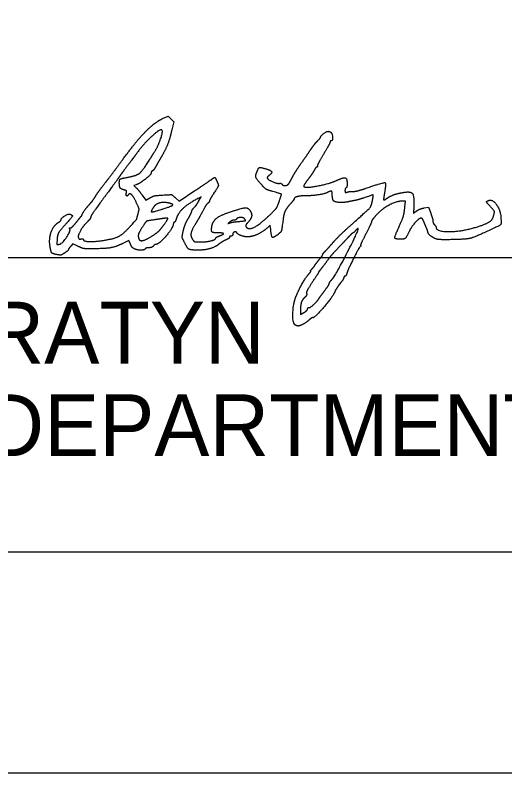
# Model space of a CAD drawing. Extents: x -21.1 to 50.3, y 0 to 22.1.
# Drawn here: x 25.904 to 27.013, y 0 to 1.718 of the extents above; entities that cross this region are included whole.
import ezdxf

# ---------------------------------------------------------------- set-up
doc = ezdxf.new("R2010")
doc.units = 0
for name, color, linetype in [('Default', 7, 'Continuous'), ('SH_Border', 7, 'Continuous'), ('SH_Cut_Line', 7, 'Continuous'), ('SH_Data', 7, 'Continuous'), ('SH_Text', 7, 'Continuous')]:
    doc.layers.add(name, color=color, linetype=linetype)

msp = doc.modelspace()

# ---------------------------------------------------------------- linework, layer by layer
at = {"layer": 'Default'}
for points in [[(26.2376, 1.4833), (26.2502, 1.4891), (26.2566, 1.4828), (26.2629, 1.4764), (26.2585, 1.4577)], [(26.1777, 1.3333), (26.1727, 1.3317), (26.1778, 1.3266)], [(26.1915, 1.3099), (26.2, 1.2984), (26.2088, 1.3036)], [(26.2666, 1.3036), (26.2748, 1.296), (26.311, 1.3201)], [(26.3205, 1.2983), (26.325, 1.3063), (26.3195, 1.3033)], [(26.7864, 1.2824), (26.7879, 1.2962), (26.78, 1.2962)], [(26.8302, 1.2808), (26.8399, 1.2823), (26.845, 1.2688)], [(26.4823, 1.2346), (26.4816, 1.2415), (26.4757, 1.2363)], [(26.1647, 1.199), (26.1613, 1.2071), (26.1475, 1.2002)], [(26.046, 1.194), (26.0345, 1.1998), (26.0295, 1.194)], [(26.55, 1.0485), (26.55, 1.0391), (26.5576, 1.0435)]]:
    msp.add_lwpolyline(points, dxfattribs=at)
for points in [[(26.148, 1.3914), (26.1777, 1.432), (26.2195, 1.4749), (26.2376, 1.4833)], [(26.2361, 1.4575), (26.2325, 1.4611), (26.1939, 1.4254), (26.1786, 1.4041)], [(26.2178, 1.4054), (26.2273, 1.4203), (26.2392, 1.4544), (26.2361, 1.4575)], [(26.2585, 1.4577), (26.2536, 1.4365), (26.2444, 1.4129), (26.235, 1.397)], [(26.5956, 1.4413), (26.5956, 1.4442), (26.6088, 1.4545), (26.6126, 1.4545)], [(26.6126, 1.4545), (26.6146, 1.4546), (26.6176, 1.4533), (26.6192, 1.4517)], [(26.6192, 1.4517), (26.6226, 1.4483), (26.623, 1.433), (26.6196, 1.433)], [(26.5752, 1.416), (26.5792, 1.4219), (26.5854, 1.4296), (26.589, 1.4332)], [(26.589, 1.4332), (26.5927, 1.4369), (26.5956, 1.4405), (26.5956, 1.4413)], [(26.6172, 1.4305), (26.6172, 1.4291), (26.6108, 1.417), (26.6028, 1.4036)], [(26.6196, 1.433), (26.6183, 1.433), (26.6172, 1.4319), (26.6172, 1.4305)], [(26.5536, 1.385), (26.5616, 1.3962), (26.5713, 1.4102), (26.5752, 1.416)], [(26.1786, 1.4041), (26.175, 1.3991), (26.1656, 1.3865), (26.1576, 1.376)], [(26.2073, 1.3887), (26.2106, 1.394), (26.2153, 1.4015), (26.2178, 1.4054)], [(26.235, 1.397), (26.2314, 1.3911), (26.2262, 1.3819), (26.2234, 1.3766)], [(26.6028, 1.4036), (26.5949, 1.3902), (26.5884, 1.3779), (26.5884, 1.3761)], [(26.1079, 1.3379), (26.1168, 1.3493), (26.1348, 1.3733), (26.148, 1.3914)], [(26.1576, 1.376), (26.1497, 1.3655), (26.1416, 1.3545), (26.1396, 1.3515)], [(26.1575, 1.3501), (26.1781, 1.3538), (26.1922, 1.3647), (26.2073, 1.3887)], [(26.2234, 1.3766), (26.2205, 1.3713), (26.2167, 1.3662), (26.2149, 1.3651)], [(26.5322, 1.3514), (26.5361, 1.3587), (26.5457, 1.3738), (26.5536, 1.385)], [(26.5884, 1.3761), (26.5884, 1.3744), (26.5875, 1.373), (26.5864, 1.373)], [(26.2116, 1.3597), (26.2116, 1.3559), (26.1859, 1.3359), (26.1777, 1.3333)], [(26.2149, 1.3651), (26.2131, 1.364), (26.2116, 1.3616), (26.2116, 1.3597)], [(26.4614, 1.3338), (26.4499, 1.3469), (26.4476, 1.3537), (26.4516, 1.3633)], [(26.4516, 1.3633), (26.4553, 1.3723), (26.4585, 1.3733), (26.4712, 1.3696)], [(26.4712, 1.3696), (26.4832, 1.366), (26.486, 1.3599), (26.4783, 1.354)], [(26.5812, 1.3664), (26.5794, 1.3628), (26.5733, 1.3537), (26.5676, 1.3462)], [(26.5864, 1.373), (26.5853, 1.373), (26.583, 1.37), (26.5812, 1.3664)], [(26.1396, 1.3515), (26.1377, 1.3486), (26.1223, 1.3276), (26.1055, 1.305)], [(26.1396, 1.338), (26.1396, 1.3448), (26.1437, 1.3476), (26.1575, 1.3501)], [(26.311, 1.3201), (26.3309, 1.3334), (26.3485, 1.3453), (26.3501, 1.3466)], [(26.3501, 1.3466), (26.3547, 1.3504), (26.357, 1.3495), (26.36, 1.3429)], [(26.36, 1.3429), (26.3644, 1.3333), (26.3635, 1.3292), (26.3532, 1.3133)], [(26.4783, 1.354), (26.4756, 1.3519), (26.4741, 1.3491), (26.4751, 1.3478)], [(26.4751, 1.3478), (26.4778, 1.344), (26.4977, 1.3358), (26.5023, 1.3366)], [(26.523, 1.3352), (26.5243, 1.3369), (26.5284, 1.3442), (26.5322, 1.3514)], [(26.5676, 1.3462), (26.5619, 1.3387), (26.5572, 1.3315), (26.5572, 1.3301)], [(26.5572, 1.3301), (26.5572, 1.3249), (26.6168, 1.3358), (26.6348, 1.3444)], [(26.6348, 1.3444), (26.6478, 1.3506), (26.6556, 1.3474), (26.6556, 1.336)], [(26.0863, 1.3086), (26.0893, 1.3134), (26.099, 1.3266), (26.1079, 1.3379)], [(26.1506, 1.3216), (26.1435, 1.3234), (26.1396, 1.3291), (26.1396, 1.338)], [(26.1778, 1.3266), (26.1806, 1.3237), (26.1868, 1.3162), (26.1915, 1.3099)], [(26.4848, 1.3187), (26.4741, 1.3218), (26.4691, 1.325), (26.4614, 1.3338)], [(26.5023, 1.3366), (26.5046, 1.3369), (26.5071, 1.3361), (26.508, 1.3347)], [(26.508, 1.3347), (26.5101, 1.3313), (26.5201, 1.3316), (26.523, 1.3352)], [(26.6532, 1.3262), (26.6519, 1.3254), (26.6508, 1.3226), (26.6508, 1.3199)], [(26.6556, 1.336), (26.6556, 1.3314), (26.6546, 1.327), (26.6532, 1.3262)], [(26.6692, 1.3183), (26.6733, 1.3181), (26.6863, 1.3213), (26.698, 1.3253)], [(26.698, 1.3253), (26.7383, 1.3392), (26.7443, 1.3375), (26.7401, 1.3137)], [(26.07, 1.2867), (26.0766, 1.294), (26.0809, 1.2997), (26.0863, 1.3086)], [(26.1557, 1.3153), (26.1566, 1.3189), (26.1554, 1.3204), (26.1506, 1.3216)], [(26.16, 1.3106), (26.1576, 1.3066), (26.1544, 1.3102), (26.1557, 1.3153)], [(26.1788, 1.2919), (26.1727, 1.3056), (26.1629, 1.3153), (26.16, 1.3106)], [(26.2088, 1.3036), (26.2154, 1.3075), (26.2229, 1.3091), (26.2381, 1.31)], [(26.2381, 1.31), (26.2584, 1.3112), (26.2585, 1.3112), (26.2666, 1.3036)], [(26.3532, 1.3133), (26.348, 1.3051), (26.3436, 1.2975), (26.3436, 1.2964)], [(26.5016, 1.2949), (26.5073, 1.3118), (26.5069, 1.3123), (26.4848, 1.3187)], [(26.5599, 1.3082), (26.5484, 1.3082), (26.5356, 1.3044), (26.5356, 1.301)], [(26.6106, 1.3156), (26.605, 1.3126), (26.5748, 1.3082), (26.5599, 1.3082)], [(26.622, 1.3109), (26.622, 1.3182), (26.6183, 1.3197), (26.6106, 1.3156)], [(26.6414, 1.2932), (26.6289, 1.2933), (26.622, 1.2996), (26.622, 1.3109)], [(26.6508, 1.3199), (26.6508, 1.316), (26.6519, 1.3154), (26.6562, 1.3168)], [(26.6562, 1.3168), (26.6592, 1.3178), (26.665, 1.3184), (26.6692, 1.3183)], [(26.7132, 1.2987), (26.7153, 1.3102), (26.7136, 1.3106), (26.6926, 1.3033)], [(26.7401, 1.3137), (26.7388, 1.3061), (26.7381, 1.2994), (26.7385, 1.299)], [(26.7461, 1.3028), (26.7533, 1.3079), (26.7716, 1.3142), (26.7852, 1.3163)], [(26.7852, 1.3163), (26.7999, 1.3186), (26.8075, 1.3082), (26.8068, 1.287)], [(26.1055, 1.305), (26.0887, 1.2823), (26.0749, 1.2622), (26.0748, 1.2602)], [(26.1821, 1.2674), (26.1847, 1.2772), (26.1844, 1.2795), (26.1788, 1.2919)], [(26.2498, 1.2923), (26.239, 1.2945), (26.2216, 1.2894), (26.2173, 1.2828)], [(26.2392, 1.2788), (26.2585, 1.2847), (26.2625, 1.2898), (26.2498, 1.2923)], [(26.3195, 1.3033), (26.2961, 1.2908), (26.2733, 1.2701), (26.2692, 1.2577)], [(26.3077, 1.2802), (26.3132, 1.2862), (26.3157, 1.2897), (26.3205, 1.2983)], [(26.3401, 1.2915), (26.3381, 1.2898), (26.335, 1.2857), (26.3332, 1.2822)], [(26.3436, 1.2964), (26.3436, 1.2953), (26.342, 1.2931), (26.3401, 1.2915)], [(26.4833, 1.2676), (26.4937, 1.2777), (26.4979, 1.2839), (26.5016, 1.2949)], [(26.5263, 1.289), (26.5178, 1.2795), (26.5121, 1.267), (26.5105, 1.2542)], [(26.5356, 1.301), (26.5356, 1.3002), (26.5314, 1.2947), (26.5263, 1.289)], [(26.658, 1.2947), (26.6547, 1.2939), (26.6472, 1.2932), (26.6414, 1.2932)], [(26.6712, 1.2973), (26.6673, 1.2966), (26.6613, 1.2954), (26.658, 1.2947)], [(26.6684, 1.2457), (26.7039, 1.2773), (26.7108, 1.2854), (26.7132, 1.2987)], [(26.6926, 1.3033), (26.6848, 1.3006), (26.6752, 1.2979), (26.6712, 1.2973)], [(26.78, 1.2962), (26.7674, 1.2962), (26.7336, 1.2778), (26.7214, 1.2642)], [(26.7385, 1.299), (26.739, 1.2985), (26.7424, 1.3002), (26.7461, 1.3028)], [(26.9768, 1.2876), (26.9715, 1.2933), (26.9713, 1.2959), (26.9759, 1.2977)], [(26.9759, 1.2977), (26.9845, 1.301), (27.0029, 1.2761), (27.0039, 1.2598)], [(26.0556, 1.2662), (26.0556, 1.2678), (26.0648, 1.2809), (26.07, 1.2867)], [(26.2173, 1.2828), (26.2102, 1.2721), (26.2148, 1.2712), (26.2392, 1.2788)], [(26.2953, 1.2561), (26.2997, 1.2637), (26.3035, 1.2714), (26.3037, 1.2732)], [(26.3037, 1.2732), (26.304, 1.2749), (26.3058, 1.2781), (26.3077, 1.2802)], [(26.3332, 1.2822), (26.3251, 1.2667), (26.3173, 1.253), (26.3111, 1.2433)], [(26.387, 1.2705), (26.4189, 1.2811), (26.4323, 1.2815), (26.4373, 1.272)], [(26.4373, 1.272), (26.4406, 1.266), (26.4372, 1.2546), (26.4297, 1.2467)], [(26.7717, 1.2346), (26.7807, 1.2545), (26.7848, 1.2676), (26.7864, 1.2824)], [(26.8068, 1.287), (26.8061, 1.2686), (26.8059, 1.2689), (26.8137, 1.2744)], [(26.8137, 1.2744), (26.8175, 1.2771), (26.8249, 1.2799), (26.8302, 1.2808)], [(26.9859, 1.2585), (26.9899, 1.2703), (26.9884, 1.2752), (26.9768, 1.2876)], [(26.003, 1.2489), (26.0055, 1.2505), (26.0076, 1.2529), (26.0077, 1.2542)], [(26.0077, 1.2542), (26.0077, 1.2579), (26.0245, 1.2679), (26.0283, 1.2665)], [(26.0283, 1.2665), (26.0342, 1.2642), (26.0319, 1.2593), (26.0176, 1.2434)], [(26.0411, 1.247), (26.0465, 1.2536), (26.0519, 1.2603), (26.0532, 1.2619)], [(26.0532, 1.2619), (26.0546, 1.2635), (26.0556, 1.2654), (26.0556, 1.2662)], [(26.0748, 1.2602), (26.0748, 1.2582), (26.0714, 1.2534), (26.0674, 1.2495)], [(26.1624, 1.2369), (26.1785, 1.2545), (26.1788, 1.255), (26.1821, 1.2674)], [(26.2374, 1.2566), (26.2318, 1.2558), (26.224, 1.2546), (26.22, 1.254)], [(26.2424, 1.245), (26.2502, 1.2563), (26.2493, 1.2585), (26.2374, 1.2566)], [(26.2692, 1.2577), (26.2675, 1.2525), (26.2652, 1.2482), (26.264, 1.2482)], [(26.2844, 1.2282), (26.286, 1.2359), (26.2909, 1.2485), (26.2953, 1.2561)], [(26.3494, 1.2394), (26.3515, 1.2507), (26.3677, 1.2641), (26.387, 1.2705)], [(26.4047, 1.2551), (26.4039, 1.254), (26.4015, 1.253), (26.3991, 1.253)], [(26.4231, 1.2562), (26.4203, 1.2596), (26.4069, 1.2588), (26.4047, 1.2551)], [(26.4072, 1.2499), (26.424, 1.2514), (26.4264, 1.2524), (26.4231, 1.2562)], [(26.4263, 1.2388), (26.4317, 1.2301), (26.4584, 1.2437), (26.4833, 1.2676)], [(26.5105, 1.2542), (26.5076, 1.2317), (26.5059, 1.2262), (26.5002, 1.2218)], [(26.7214, 1.2642), (26.7156, 1.2578), (26.7108, 1.2512), (26.7108, 1.2496)], [(26.8232, 1.2578), (26.8189, 1.2578), (26.8007, 1.2373), (26.796, 1.2271)], [(26.8288, 1.2512), (26.8273, 1.2548), (26.8248, 1.2578), (26.8232, 1.2578)], [(26.845, 1.2688), (26.8477, 1.2613), (26.85, 1.2532), (26.85, 1.2507)], [(26.9371, 1.2342), (26.9607, 1.2404), (26.9837, 1.2518), (26.9859, 1.2585)], [(27.0039, 1.2598), (27.0049, 1.2445), (27.0022, 1.2413), (26.9788, 1.2304)], [(25.9828, 1.1926), (25.9798, 1.2111), (25.9906, 1.2411), (26.003, 1.2489)], [(26.0176, 1.2434), (26.0039, 1.2282), (25.9989, 1.2181), (25.9984, 1.2043)], [(26.0288, 1.2357), (26.0302, 1.2353), (26.0358, 1.2404), (26.0411, 1.247)], [(26.0674, 1.2495), (26.0576, 1.2399), (26.0452, 1.2177), (26.047, 1.2131)], [(26.1059, 1.2076), (26.1287, 1.2113), (26.1483, 1.2215), (26.1624, 1.2369)], [(26.1929, 1.239), (26.1847, 1.2264), (26.1816, 1.2166), (26.1838, 1.2108)], [(26.22, 1.254), (26.2023, 1.2514), (26.2002, 1.2503), (26.1929, 1.239)], [(26.2125, 1.2163), (26.2237, 1.2233), (26.2347, 1.2338), (26.2424, 1.245)], [(26.262, 1.2452), (26.2619, 1.2367), (26.2288, 1.1978), (26.2216, 1.1978)], [(26.264, 1.2482), (26.2629, 1.2482), (26.262, 1.2469), (26.262, 1.2452)], [(26.3111, 1.2433), (26.3032, 1.2307), (26.3009, 1.2154), (26.306, 1.2086)], [(26.363, 1.2242), (26.3515, 1.2242), (26.3474, 1.2288), (26.3494, 1.2394)], [(26.3903, 1.2492), (26.3857, 1.2455), (26.3857, 1.2455), (26.3904, 1.2471)], [(26.3991, 1.253), (26.3968, 1.253), (26.3929, 1.2513), (26.3903, 1.2492)], [(26.3904, 1.2471), (26.3931, 1.248), (26.4006, 1.2493), (26.4072, 1.2499)], [(26.4297, 1.2467), (26.427, 1.2438), (26.4254, 1.2402), (26.4263, 1.2388)], [(26.6243, 1.203), (26.6316, 1.2114), (26.6514, 1.2306), (26.6684, 1.2457)], [(26.7108, 1.2496), (26.7108, 1.2481), (26.7049, 1.2352), (26.6976, 1.2211)], [(26.8348, 1.2371), (26.833, 1.2412), (26.8303, 1.2476), (26.8288, 1.2512)], [(26.8381, 1.2275), (26.8381, 1.2286), (26.8366, 1.2329), (26.8348, 1.2371)], [(26.85, 1.2507), (26.85, 1.2482), (26.8517, 1.2445), (26.8536, 1.2426)], [(26.8536, 1.2426), (26.8556, 1.2406), (26.8572, 1.2379), (26.8572, 1.2366)], [(26.0032, 1.1983), (26.0095, 1.1992), (26.0296, 1.2276), (26.0276, 1.2328)], [(26.0276, 1.2328), (26.0269, 1.2348), (26.0274, 1.2361), (26.0288, 1.2357)], [(26.2864, 1.2042), (26.2819, 1.2133), (26.2817, 1.2156), (26.2844, 1.2282)], [(26.3663, 1.2173), (26.3766, 1.221), (26.3751, 1.2242), (26.363, 1.2242)], [(26.3964, 1.2204), (26.3964, 1.2185), (26.3948, 1.217), (26.3928, 1.217)], [(26.4059, 1.2244), (26.4039, 1.2277), (26.3964, 1.2245), (26.3964, 1.2204)], [(26.4372, 1.2159), (26.4286, 1.2143), (26.4088, 1.2197), (26.4059, 1.2244)], [(26.4757, 1.2363), (26.4664, 1.2282), (26.4464, 1.2175), (26.4372, 1.2159)], [(26.5002, 1.2218), (26.4885, 1.2125), (26.4841, 1.2157), (26.4823, 1.2346)], [(26.6217, 1.1191), (26.6294, 1.1279), (26.6826, 1.2316), (26.6805, 1.2337)], [(26.6691, 1.2242), (26.6683, 1.2242), (26.6643, 1.2207), (26.6603, 1.2164)], [(26.6748, 1.2296), (26.6724, 1.2266), (26.6698, 1.2242), (26.6691, 1.2242)], [(26.6805, 1.2337), (26.6798, 1.2344), (26.6772, 1.2326), (26.6748, 1.2296)], [(26.6976, 1.2211), (26.6903, 1.207), (26.6852, 1.1954), (26.6862, 1.1954)], [(26.7791, 1.2098), (26.7645, 1.2098), (26.7629, 1.2152), (26.7717, 1.2346)], [(26.796, 1.2271), (26.7902, 1.2147), (26.7854, 1.2098), (26.7791, 1.2098)], [(26.8538, 1.2119), (26.8467, 1.2152), (26.8383, 1.2236), (26.8381, 1.2275)], [(26.8572, 1.2366), (26.8572, 1.228), (26.9078, 1.2265), (26.9371, 1.2342)], [(26.9788, 1.2304), (26.944, 1.214), (26.923, 1.2093), (26.8836, 1.2088)], [(25.9984, 1.2043), (25.9981, 1.1986), (25.9989, 1.1976), (26.0032, 1.1983)], [(26.047, 1.2131), (26.0479, 1.2107), (26.0503, 1.2097), (26.0533, 1.2105)], [(26.0533, 1.2105), (26.0559, 1.2112), (26.058, 1.2109), (26.058, 1.2098)], [(26.058, 1.2098), (26.058, 1.2051), (26.0837, 1.204), (26.1059, 1.2076)], [(26.1838, 1.2108), (26.1858, 1.2055), (26.1994, 1.2081), (26.2125, 1.2163)], [(26.3181, 1.1851), (26.3006, 1.1852), (26.2936, 1.1894), (26.2864, 1.2042)], [(26.306, 1.2086), (26.3089, 1.2048), (26.3124, 1.2039), (26.3236, 1.2038)], [(26.3236, 1.2038), (26.3376, 1.2038), (26.358, 1.2089), (26.358, 1.2124)], [(26.358, 1.2124), (26.358, 1.2135), (26.3618, 1.2157), (26.3663, 1.2173)], [(26.3838, 1.2097), (26.3765, 1.2063), (26.3689, 1.2018), (26.3646, 1.1983)], [(26.3892, 1.2146), (26.3892, 1.2132), (26.3868, 1.211), (26.3838, 1.2097)], [(26.3928, 1.217), (26.3909, 1.217), (26.3892, 1.2159), (26.3892, 1.2146)], [(26.6059, 1.1826), (26.6088, 1.1854), (26.6171, 1.1946), (26.6243, 1.203)], [(26.6603, 1.2164), (26.6562, 1.2121), (26.6456, 1.201), (26.6368, 1.1918)], [(26.8836, 1.2088), (26.8687, 1.2087), (26.8584, 1.2097), (26.8538, 1.2119)], [(25.9994, 1.1748), (25.9885, 1.1769), (25.9846, 1.181), (25.9828, 1.1926)], [(26.0244, 1.1864), (26.0244, 1.1854), (26.0206, 1.1821), (26.0161, 1.1789)], [(26.0295, 1.194), (26.0267, 1.1908), (26.0244, 1.1874), (26.0244, 1.1864)], [(26.0768, 1.1882), (26.0612, 1.1882), (26.0553, 1.1893), (26.046, 1.194)], [(26.1475, 1.2002), (26.1319, 1.1925), (26.1067, 1.1882), (26.0768, 1.1882)], [(26.1729, 1.1884), (26.1702, 1.1898), (26.1665, 1.1946), (26.1647, 1.199)], [(26.1984, 1.1882), (26.1965, 1.185), (26.179, 1.1852), (26.1729, 1.1884)], [(26.2067, 1.1906), (26.203, 1.1906), (26.1992, 1.1895), (26.1984, 1.1882)], [(26.2164, 1.1942), (26.2148, 1.1922), (26.2104, 1.1906), (26.2067, 1.1906)], [(26.2216, 1.1978), (26.2204, 1.1978), (26.2181, 1.1962), (26.2164, 1.1942)], [(26.3646, 1.1983), (26.3569, 1.1919), (26.3326, 1.185), (26.3181, 1.1851)], [(26.6368, 1.1918), (26.628, 1.1825), (26.6181, 1.1713), (26.6148, 1.1668)], [(26.6854, 1.1936), (26.6828, 1.1918), (26.6575, 1.1408), (26.6546, 1.1312)], [(26.6862, 1.1954), (26.6872, 1.1954), (26.6869, 1.1946), (26.6854, 1.1936)], [(26.0161, 1.1789), (26.0095, 1.1745), (26.0059, 1.1736), (25.9994, 1.1748)], [(26.5938, 1.1655), (26.5975, 1.1698), (26.6004, 1.1742), (26.6005, 1.1753)], [(26.6005, 1.1753), (26.6005, 1.1765), (26.6029, 1.1797), (26.6059, 1.1826)], [(26.5758, 1.1422), (26.5781, 1.1446), (26.5817, 1.1491), (26.5836, 1.1522)], [(26.5836, 1.1522), (26.5856, 1.1553), (26.5902, 1.1613), (26.5938, 1.1655)], [(26.6148, 1.1668), (26.6068, 1.1559), (26.5962, 1.1421), (26.5933, 1.1385)], [(26.57, 1.1324), (26.5727, 1.1354), (26.5741, 1.1378), (26.5732, 1.1378)], [(26.5732, 1.1378), (26.5724, 1.1378), (26.5735, 1.1398), (26.5758, 1.1422)], [(26.5908, 1.1346), (26.5908, 1.1341), (26.5845, 1.1241), (26.5768, 1.1125)], [(26.5933, 1.1385), (26.5919, 1.1369), (26.5908, 1.1352), (26.5908, 1.1346)], [(26.5398, 1.0798), (26.5457, 1.0946), (26.5629, 1.1246), (26.57, 1.1324)], [(26.6148, 1.1088), (26.6148, 1.1102), (26.6179, 1.1148), (26.6217, 1.1191)], [(26.6484, 1.1233), (26.6484, 1.1219), (26.6442, 1.1152), (26.639, 1.1083)], [(26.6507, 1.1258), (26.6494, 1.1258), (26.6484, 1.1247), (26.6484, 1.1233)], [(26.6546, 1.1312), (26.6537, 1.1282), (26.6519, 1.1258), (26.6507, 1.1258)], [(26.5768, 1.1125), (26.5681, 1.0995), (26.5631, 1.0897), (26.5638, 1.087)], [(26.6046, 1.093), (26.6102, 1.1004), (26.6148, 1.1075), (26.6148, 1.1088)], [(26.639, 1.1083), (26.6337, 1.1014), (26.6286, 1.0934), (26.6276, 1.0905)], [(26.5638, 1.087), (26.5645, 1.0845), (26.5629, 1.0809), (26.5602, 1.0784)], [(26.6276, 1.0905), (26.6239, 1.0807), (26.5827, 1.0322), (26.5781, 1.0322)], [(26.592, 1.0758), (26.5934, 1.0779), (26.599, 1.0856), (26.6046, 1.093)], [(26.538, 1.0154), (26.5321, 1.0191), (26.5333, 1.0634), (26.5398, 1.0798)], [(26.5602, 1.0784), (26.5542, 1.0732), (26.55, 1.0609), (26.55, 1.0485)], [(26.5692, 1.055), (26.5712, 1.0538), (26.5878, 1.069), (26.592, 1.0758)], [(26.5576, 1.0435), (26.5617, 1.0459), (26.5656, 1.0497), (26.5662, 1.052)], [(26.5662, 1.052), (26.5669, 1.0543), (26.5682, 1.0556), (26.5692, 1.055)], [(26.5781, 1.0322), (26.5767, 1.0322), (26.5733, 1.0302), (26.5706, 1.0277)], [(26.5446, 1.0131), (26.5429, 1.0131), (26.54, 1.0141), (26.538, 1.0154)], [(26.5706, 1.0277), (26.5644, 1.0219), (26.5485, 1.013), (26.5446, 1.0131)]]:
    msp.add_open_spline(points, degree=2, dxfattribs=at)
at = {"layer": 'SH_Border'}
msp.add_lwpolyline([(1.5, 21.5), (33.5, 21.5), (33.5, 0.5), (1.5, 0.5)], close=True, dxfattribs=at)
at = {"layer": 'SH_Cut_Line'}
msp.add_lwpolyline([(0, 0), (34, 0), (34, 22), (0, 22)], close=True, dxfattribs=at)
at = {"layer": 'SH_Data'}
msp.add_line((24.7523, 1.1681), (28.2523, 1.1681), dxfattribs=at)
at = {"layer": 'SH_Text'}
msp.add_line((26.7289, 1.2853), (26.7289, 1.2853), dxfattribs=at)

# ---------------------------------------------------------------- texts
for s, p in [('PAMELA BORATYN', (24.7523, 0.9281)), ('DIRECTOR, DEPARTMENT OF TRANSPORTATION', (24.7523, 0.7181))]:
    msp.add_text(s, height=0.14, dxfattribs=at).set_placement(p)

doc.saveas('drawing.dxf')
